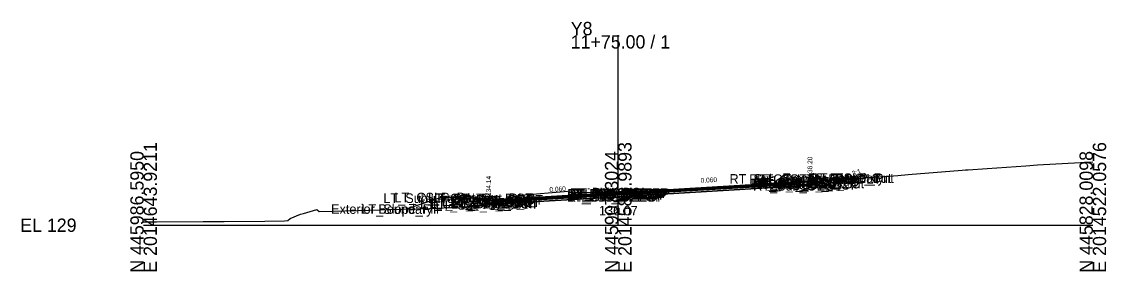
# Model space of a CAD drawing. Extents: x -26 to 1403, y -10 to 8043.
# Drawn here: x -25.7 to 202.8, y 3490.3 to 3542.8 of the extents above; entities that cross this region are included whole.
import ezdxf

# ---------------------------------------------------------------- set-up
doc = ezdxf.new("R2010")
doc.units = 0
for name, color, linetype in [('Default', 7, 'Continuous'), ('Exist Cross Section Cell', 7, 'Continuous'), ('Exist XS Center Line Elevation Label', 7, 'Continuous'), ('Exist XS Ground Line', 7, 'Continuous'), ('Prop CMT Conc Surface', 7, 'Continuous'), ('Prop CMT Concrete Structures', 7, 'Continuous'), ('Prop CMT Pvmt Course 1', 7, 'Continuous'), ('Prop CMT Pvmt Course 1 CG', 7, 'Continuous'), ('Prop CMT Pvmt Course 2', 7, 'Continuous'), ('Prop CMT Pvmt Course 3', 7, 'Continuous'), ('Prop CMT Pvmt Surface', 7, 'Continuous'), ('Prop CMT Slope Grass', 7, 'Continuous'), ('Prop CMT Subgrade Earthwork', 7, 'Continuous'), ('Prop XS Earthwork Shape', 7, 'Continuous'), ('Prop XS Hydro Elevations', 7, 'Continuous'), ('Prop XS SE Text', 7, 'Continuous'), ('Prop XS Side Slope Text', 7, 'Continuous'), ('Scratch_Level_0', 7, 'Continuous')]:
    doc.layers.add(name, color=color, linetype=linetype)

msp = doc.modelspace()

# ---------------------------------------------------------------- linework, layer by layer
at = {"layer": 'Exist Cross Section Cell'}
for p, q in [((100, 3500), (100, 3539.96)), ((0, 3500), (100, 3500)), ((100, 3500), (200, 3500))]:
    msp.add_line(p, q, dxfattribs=at)
at = {"layer": 'Exist XS Ground Line'}
msp.add_lwpolyline([(0, 3500.74), (0.56, 3500.73), (1.18, 3500.74), (1.51, 3500.74), (2.71, 3500.72), (12.51, 3500.76), (17, 3500.78), (25.51, 3500.88), (29.66, 3500.95), (30.37, 3501), (30.87, 3501.4), (33.07, 3502.34), (33.65, 3502.44), (36.49, 3503.27), (36.99, 3502.87), (45.11, 3503.07), (51.94, 3503.3), (57.6, 3503.44), (60.2, 3503.52), (66.2, 3503.82), (72.18, 3504.23), (79.64, 3504.74), (80.23, 3506.36), (88.6, 3507.09), (90.11, 3507.26), (90.55, 3506.81), (94.3, 3506.92), (100, 3507.07), (100.93, 3507.09), (106.48, 3507.17), (112.57, 3507.11), (112.57, 3507.28), (123.27, 3508), (136.3, 3508.9), (136.85, 3508.94), (147.36, 3509.71), (156.09, 3510.26), (158.92, 3510.47), (161.1, 3510.64), (172.5, 3511.6), (173.19, 3511.66), (173.71, 3511.68), (177.74, 3511.96), (185.89, 3512.52), (188.34, 3512.71), (200, 3513.32)], dxfattribs=at)
at = {"layer": 'Prop CMT Conc Surface'}
for points in [[(138.39, 3509.16), (140.39, 3509.2)], [(140.39, 3509.2), (140.39, 3509.7), (140.89, 3509.7)], [(72.68, 3505.14), (72.68, 3505.64), (72.18, 3505.64)], [(74.68, 3505.34), (72.68, 3505.14)]]:
    msp.add_lwpolyline(points, dxfattribs=at)
at = {"layer": 'Prop CMT Concrete Structures'}
for points in [[(138.39, 3509.16), (140.39, 3509.2), (140.39, 3509.7), (140.89, 3509.7)], [(140.89, 3509.7), (140.89, 3508.73), (138.39, 3508.58)], [(138.39, 3508.58), (138.39, 3509.16)], [(74.68, 3505.34), (72.68, 3505.14), (72.68, 3505.64), (72.18, 3505.64)], [(72.18, 3505.64), (72.18, 3504.6), (74.68, 3504.75)], [(74.68, 3504.75), (74.68, 3505.34)]]:
    msp.add_lwpolyline(points, dxfattribs=at)
at = {"layer": 'Prop CMT Pvmt Course 1'}
for points in [[(100, 3506.86), (138.39, 3509.16)], [(138.39, 3508.91), (100, 3506.61)], [(138.39, 3509.16), (138.39, 3508.91)], [(100, 3506.86), (74.68, 3505.34)], [(74.68, 3505.09), (100, 3506.61)], [(100, 3506.61), (100, 3506.86)], [(100, 3506.61), (100, 3506.86)], [(74.68, 3505.34), (74.68, 3505.09)]]:
    msp.add_lwpolyline(points, dxfattribs=at)
msp.add_lwpolyline([(100, 3506.61), (100, 3506.73), (100, 3506.73), (100, 3506.61)], close=True, dxfattribs=at)
msp.add_lwpolyline([(100, 3506.61), (100, 3506.73), (100, 3506.73), (100, 3506.61)], close=True, dxfattribs=at)
at = {"layer": 'Prop CMT Pvmt Course 1 CG'}
for points in [[(138.39, 3508.58), (141.39, 3508.76), (141.67, 3508.48)], [(138.39, 3508.29), (138.39, 3508.58)], [(141.67, 3508.48), (138.39, 3508.29)], [(74.68, 3504.75), (71.68, 3504.57), (71.37, 3504.26)], [(71.37, 3504.26), (74.68, 3504.46)], [(74.68, 3504.46), (74.68, 3504.75)]]:
    msp.add_lwpolyline(points, dxfattribs=at)
at = {"layer": 'Prop CMT Pvmt Course 2'}
for points in [[(100, 3506.61), (138.39, 3508.91)], [(138.39, 3508.66), (100, 3506.36)], [(138.39, 3508.91), (138.39, 3508.66)], [(100, 3506.61), (74.68, 3505.09)], [(74.68, 3504.84), (100, 3506.36)], [(100, 3506.36), (100, 3506.61)], [(100, 3506.36), (100, 3506.61)], [(74.68, 3505.09), (74.68, 3504.84)]]:
    msp.add_lwpolyline(points, dxfattribs=at)
at = {"layer": 'Prop CMT Pvmt Course 3'}
for points in [[(100, 3506.36), (138.39, 3508.66)], [(138.39, 3508.29), (100, 3505.98)], [(138.39, 3508.66), (138.39, 3508.29)], [(100, 3506.36), (74.68, 3504.84)], [(74.68, 3504.46), (100, 3505.98)], [(100, 3505.98), (100, 3506.36)], [(100, 3505.98), (100, 3506.36)], [(74.68, 3504.84), (74.68, 3504.46)]]:
    msp.add_lwpolyline(points, dxfattribs=at)
at = {"layer": 'Prop CMT Pvmt Surface'}
for points in [[(100, 3506.86), (138.39, 3509.16)], [(100, 3506.86), (74.68, 3505.34)]]:
    msp.add_lwpolyline(points, dxfattribs=at)
at = {"layer": 'Prop CMT Slope Grass'}
for points in [[(140.89, 3509.7), (150.39, 3509.89), (150.42, 3509.9)], [(72.18, 3505.64), (62.68, 3505.83), (55.35, 3503.39)]]:
    msp.add_lwpolyline(points, dxfattribs=at)
at = {"layer": 'Prop CMT Subgrade Earthwork'}
for points in [[(100, 3505.98), (138.39, 3508.29)], [(138.39, 3508.29), (141.67, 3508.48), (142.93, 3509.74)], [(100, 3505.98), (74.68, 3504.46)], [(74.68, 3504.46), (71.37, 3504.26), (69.95, 3505.68)]]:
    msp.add_lwpolyline(points, dxfattribs=at)
at = {"layer": 'Prop XS Earthwork Shape'}
for points in [[(104.82, 3507.15), (106.48, 3507.17), (112.57, 3507.11), (112.57, 3507.28), (123.27, 3508), (136.3, 3508.9), (136.85, 3508.94), (138.39, 3509.05), (138.39, 3508.58), (140.89, 3508.73), (140.89, 3509.24), (142.54, 3509.36), (141.67, 3508.48), (138.39, 3508.29), (100, 3505.98), (79.65, 3504.76), (79.98, 3505.66), (100, 3506.86)], [(138.39, 3509.05), (140.39, 3509.2), (140.89, 3509.24), (140.89, 3508.73), (138.39, 3508.58)], [(142.54, 3509.36), (142.93, 3509.74), (150.22, 3509.89), (147.36, 3509.71)], [(150.22, 3509.89), (150.42, 3509.9), (150.39, 3509.89)], [(74.68, 3504.46), (71.37, 3504.26), (69.95, 3505.68), (62.68, 3505.83), (55.35, 3503.39), (57.6, 3503.44), (60.2, 3503.52), (66.2, 3503.82), (72.18, 3504.23), (79.64, 3504.74), (79.65, 3504.76)], [(79.98, 3505.66), (80.23, 3506.36), (88.6, 3507.09), (90.11, 3507.26), (90.55, 3506.81), (94.3, 3506.92), (100, 3507.07), (100.93, 3507.09), (104.82, 3507.15), (100, 3506.86)]]:
    msp.add_lwpolyline(points, close=True, dxfattribs=at)

# ---------------------------------------------------------------- texts
at = {"layer": 'Default'}
msp.add_text('-', height=0.0001, dxfattribs=at).set_placement((0, 3500))
at = {"layer": 'Exist Cross Section Cell'}
for s, p in [('Y8', (90, 3539.96)), ('11+75.00 / 1', (90, 3537.16)), ('EL 129', (-26, 3498.6))]:
    msp.add_text(s, height=2.8, dxfattribs=at).set_placement(p)
for s, p in [('E 2014643.9211', (2.8, 3490)), ('E 2014582.9893', (102.8, 3490)), ('E 2014522.0576', (202.8, 3490)), ('N 445986.5950', (0, 3490)), ('N 445907.3024', (100, 3490)), ('N 445828.0098', (200, 3490))]:
    msp.add_text(s, height=2.8, rotation=90, dxfattribs=at).set_placement(p)
at = {"layer": 'Exist XS Center Line Elevation Label'}
msp.add_text('136.07', height=2, dxfattribs=at).set_placement((95.94, 3502.07))
at = {"layer": 'Prop XS Hydro Elevations'}
for s, p in [('138.20', (140.89, 3510.2)), ('134.14', (73.18, 3506.14))]:
    msp.add_text(s, height=1, rotation=90, dxfattribs=at).set_placement(p)
at = {"layer": 'Prop XS SE Text'}
for p in [(85.53, 3506.99), (117.39, 3508.9)]:
    msp.add_text('0.060', height=1, rotation=3.4336, dxfattribs=at).set_placement(p)
at = {"layer": 'Prop XS Side Slope Text'}
for p in [(149.42, 3510.36), (58.03, 3505.07)]:
    msp.add_text('3:1', height=1, rotation=18.4332, dxfattribs=at).set_placement(p)
at = {"layer": 'Scratch_Level_0'}
for s, p in [('RT_Sub_Trench_Out_DLT', (123.44, 3508.74)), ('RT_CG_Top_Face', (127.6, 3508.7)), ('RT_CG_Top_BOC', (129.13, 3508.7)), ('Exterior Boundary', (134.56, 3508.9)), ('RT_Slope_Cut', (140.01, 3508.9)), ('RT_CSLP_Pnt', (140.52, 3508.89)), ('RT_CG1_Shelf_Out', (127.89, 3507.76)), ('RT_CG_Bot_IE', (128.26, 3507.58)), ('RT_Sub_OEOT', (128.42, 3507.29)), ('RT_PV2_OEOT', (128.52, 3507.91)), ('RT_PV3_OEOT', (128.52, 3507.66)), ('RT_CG_Top_Gut', (128.58, 3508.2)), ('RT_PV1_OEOT', (129.08, 3508.16)), ('RT_CG_Bot_BOC', (129.16, 3507.73)), ('RT_Sub_OEOP', (131.73, 3507.48)), ('LT_Sub_Trench_Out_DLT', (50.52, 3504.68)), ('LT_CSLP_Pnt', (52.85, 3504.83)), ('LT_CG_Top_Face', (59.94, 3504.64)), ('LT_CG_Top_BOC', (60.46, 3504.64)), ('LT_CG_Top_Gut', (60.91, 3504.14)), ('LT_CG_Bot_IE', (64.59, 3503.75)), ('LT_PV2_OEOT', (64.85, 3504.09)), ('LT_PV3_OEOT', (64.85, 3503.84)), ('LT_PV1_OEOT', (65.42, 3504.34)), ('RT_Sub_OEEOP', (89.17, 3504.98)), ('LT_Sub_OEEOP', (89.21, 3504.98)), ('RT_PV2_OEEOP', (89.26, 3505.61)), ('RT_PV3_OEEOP', (89.26, 3505.36)), ('LT_PV2_OEEOP', (89.31, 3505.61)), ('LT_PV3_OEEOP', (89.31, 3505.36)), ('RT_PV1_OEEOP', (89.83, 3505.73)), ('LT_PV1_OEEOP', (89.87, 3505.73)), ('RT_PV2_IEEOP', (89.91, 3505.61)), ('LT_PV2_IEEOP', (89.95, 3505.61)), ('RT_PV1_IEEOP', (90.47, 3505.73)), ('LT_PV1_IEEOP', (90.52, 3505.73)), ('PV2_PGL', (93.91, 3505.61)), ('PV1_PGL', (94.47, 3505.86)), ('Exterior Boundary', (39.49, 3502.39)), ('LT_Slope_Fill', (45.87, 3502.39)), ('LT_CG1_Shelf_Out', (58.23, 3503.57)), ('LT_CG_Bot_BOC', (60.49, 3503.6)), ('LT_Sub_OEOP', (61.48, 3503.26)), ('LT_Sub_OEOT', (64.76, 3503.46))]:
    msp.add_text(s, height=2, dxfattribs=at).set_placement(p)

doc.saveas('drawing.dxf')
